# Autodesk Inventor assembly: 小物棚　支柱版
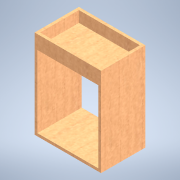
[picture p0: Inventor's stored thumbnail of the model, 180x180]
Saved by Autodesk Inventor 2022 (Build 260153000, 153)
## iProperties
Created: 2024-12
Part Number: 小物棚　支柱版
Document SubType Name: Assembly
Designer: shimizu
Mass: 25.0986 g
Surface Area: 290.012 cm^2
Volume: 31.3733 cm^3
Density: 0.8 g/cm^3
Author: shimizu
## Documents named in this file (7)
- C:\Users\shimizu\Documents\卒論2024\3DCAD\小物棚 - 支柱版\組立図\小物棚　支柱版.iam
- C:\Users\shimizu\Documents\卒論2024\3DCAD\小物棚 - 支柱版\部品図\底板.ipt
- C:\Users\shimizu\Documents\卒論2024\3DCAD\小物棚 - 支柱版\部品図\側板.ipt
- C:\Users\shimizu\Documents\卒論2024\3DCAD\小物棚 - 支柱版\部品図\側板②.ipt
- C:\Users\shimizu\Documents\卒論2024\3DCAD\小物棚 - 支柱版\部品図\天板.ipt
- C:\Users\shimizu\Documents\卒論2024\3DCAD\小物棚 - 支柱版\部品図\側板③.ipt
- C:\Users\shimizu\Documents\卒論2024\3DCAD\小物棚 - 支柱版\部品図\支柱.ipt
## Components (7 placed, 6 different names)
1. 底板:1 — メイト:1, フラッシュ:1, フラッシュ:2, メイト:2, フラッシュ:3, フラッシュ:4
2. 側板:1 — メイト:2, フラッシュ:3, フラッシュ:4, フラッシュ:5, メイト:4, メイト:5, メイト:6, フラッシュ:11
3. 側板②:1 — メイト:1, フラッシュ:1, フラッシュ:2, フラッシュ:6, メイト:3, フラッシュ:7, フラッシュ:8, フラッシュ:9, フラッシュ:10
4. 天板:1 — フラッシュ:5, フラッシュ:6, メイト:3
5. 側板③:1 — メイト:4, フラッシュ:7, フラッシュ:8
6. 側板③:2 — メイト:5, フラッシュ:9, フラッシュ:10, メイト:7
7. 支柱:1 — メイト:6, フラッシュ:11, メイト:7
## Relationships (18: Flush 11, Mate 7)
- メイト:1 [Mate]: 底板:1 ↔ 側板②:1
- フラッシュ:1 [Flush]: 底板:1 ↔ 側板②:1
- フラッシュ:2 [Flush]: 底板:1 ↔ 側板②:1
- メイト:2 [Mate]: 底板:1 ↔ 側板:1
- フラッシュ:3 [Flush]: 底板:1 ↔ 側板:1
- フラッシュ:4 [Flush]: 底板:1 ↔ 側板:1
- フラッシュ:5 [Flush]: 側板:1 ↔ 天板:1
- フラッシュ:6 [Flush]: 側板②:1 ↔ 天板:1
- メイト:3 [Mate]: 側板②:1 ↔ 天板:1
- メイト:4 [Mate]: 側板:1 ↔ 側板③:1
- フラッシュ:7 [Flush]: 側板②:1 ↔ 側板③:1
- フラッシュ:8 [Flush]: 側板②:1 ↔ 側板③:1
- メイト:5 [Mate]: 側板:1 ↔ 側板③:2
- フラッシュ:9 [Flush]: 側板②:1 ↔ 側板③:2
- フラッシュ:10 [Flush]: 側板②:1 ↔ 側板③:2
- メイト:6 [Mate]: 側板:1 ↔ 支柱:1
- フラッシュ:11 [Flush]: 側板:1 ↔ 支柱:1
- メイト:7 [Mate]: 側板③:2 ↔ 支柱:1
## Named parameters: sa_0 = 50000 mm
